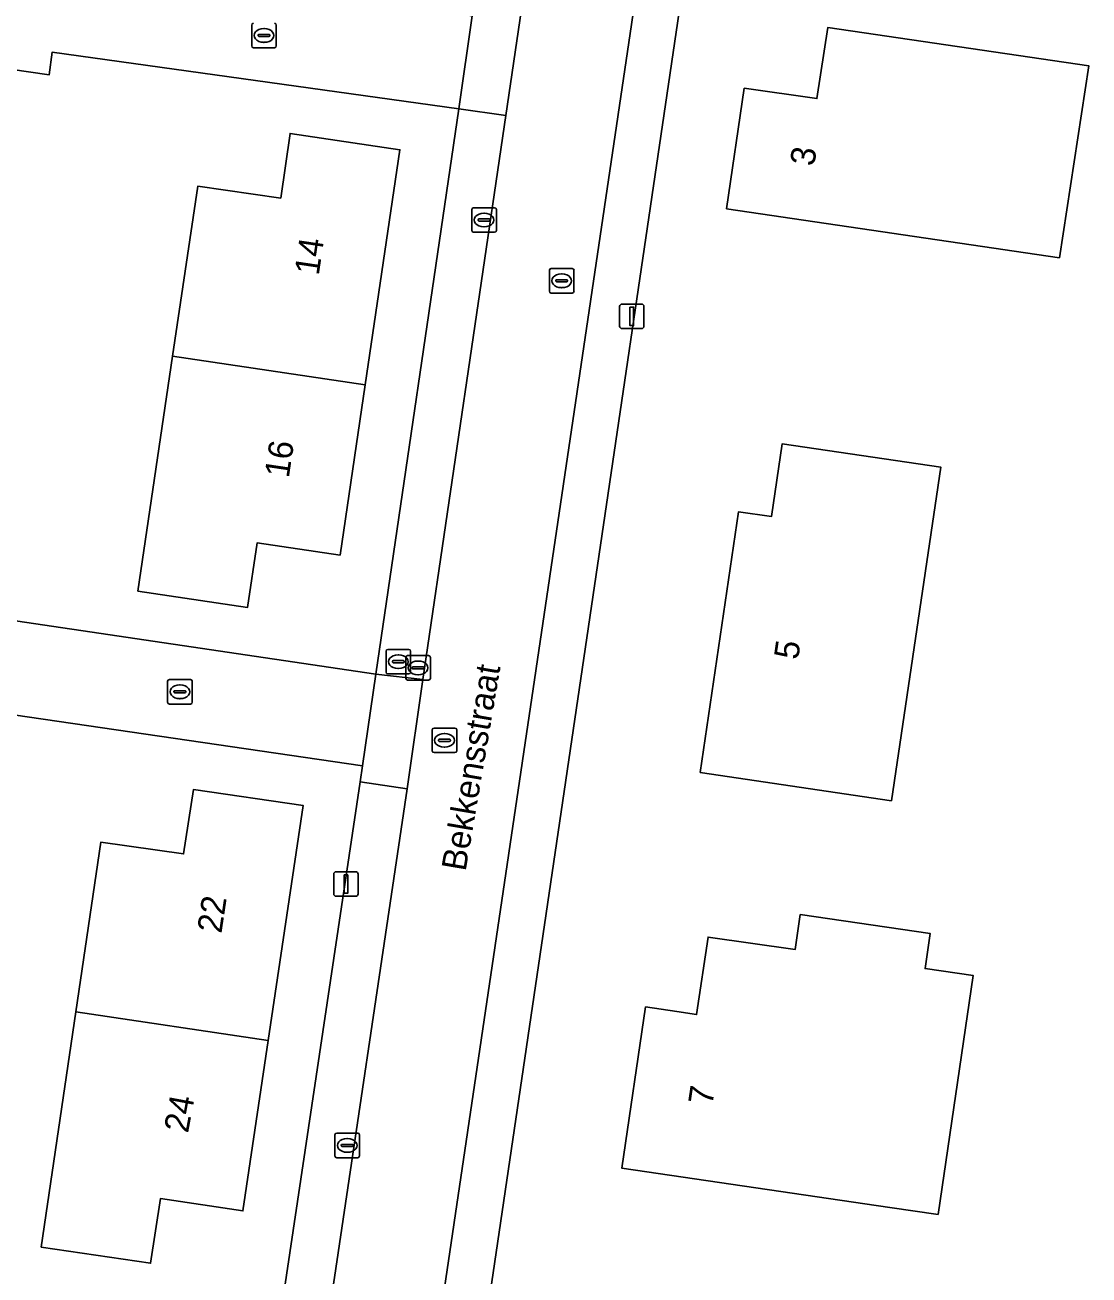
# Model space of a CAD drawing. Extents: x 164148 to 165261, y 382513 to 383432.
# Drawn here: x 164534 to 164577.3, y 383084.8 to 383135.7 of the extents above; entities that cross this region are included whole.
import ezdxf

# ---------------------------------------------------------------- set-up
doc = ezdxf.new("R2010")
doc.units = 0
for name, color, linetype in [('IMGEO_Brandkraan', 7, 'Continuous'), ('IMGEO_Erf', 7, 'Continuous'), ('IMGEO_Kolk', 7, 'Continuous'), ('IMGEO_Lichtmast', 7, 'Continuous'), ('IMGEO_Openbare_ruimte_label', 7, 'Continuous'), ('IMGEO_Pand', 7, 'Continuous'), ('IMGEO_Pand_nummerreeks', 7, 'Continuous'), ('IMGEO_Parkeervlak_open', 7, 'Continuous'), ('IMGEO_Rijbaan_lokaal_open', 7, 'Continuous'), ('IMGEO_Rioolput', 7, 'Continuous'), ('IMGEO_Voetpad_gesloten', 7, 'Continuous'), ('IMGEO_Voetpad_open', 7, 'Continuous')]:
    doc.layers.add(name, color=color, linetype=linetype)

msp = doc.modelspace()

# ---------------------------------------------------------------- linework, layer by layer
at = {"layer": 'IMGEO_Brandkraan'}
for p, q in [((164548.716, 383109.375), (164548.716, 383110.227)), ((164548.791, 383110.301), (164549.643, 383110.301)), ((164549.204, 383110.081), (164549.229, 383110.081)), ((164549.717, 383110.227), (164549.717, 383109.375)), ((164548.975, 383109.795), (164548.975, 383109.807)), ((164549.413, 383109.758), (164549.015, 383109.758)), ((164549.018, 383109.844), (164549.416, 383109.844)), ((164549.227, 383109.521), (164549.202, 383109.521)), ((164549.459, 383109.807), (164549.459, 383109.795)), ((164549.643, 383109.301), (164548.791, 383109.301))]:
    msp.add_line(p, q, dxfattribs=at)
for points in [[(164548.716, 383109.375), (164548.716, 383110.227)], [(164548.791, 383110.301), (164549.643, 383110.301)], [(164549.717, 383110.227), (164549.717, 383109.375)], [(164549.643, 383109.301), (164548.791, 383109.301)]]:
    msp.add_lwpolyline(points, dxfattribs=at)
for centre, radius, start, end in [((164548.793, 383110.225), 0.0765, 91.552, 178.448), ((164548.793, 383110.225), 0.0765, 91.552, 178.448), ((164549.641, 383110.225), 0.0765, 1.552, 88.448), ((164549.641, 383110.225), 0.0765, 1.552, 88.448), ((164548.793, 383109.377), 0.0765, 181.552, 268.448), ((164548.793, 383109.377), 0.0765, 181.552, 268.448), ((164549.015, 383109.804), 0.0403, 85.8775, 175.7526), ((164549.012, 383109.794), 0.0366, 178.938, 274.7102), ((164549.416, 383109.801), 0.043, 264.8664, 352.4533), ((164549.42, 383109.806), 0.0386, 1.7309, 96.639), ((164549.641, 383109.377), 0.0765, 271.552, 358.448), ((164549.641, 383109.377), 0.0765, 271.552, 358.448)]:
    msp.add_arc(centre, radius, start, end, dxfattribs=at)
for centre, major_axis, ratio, start_param, end_param in [((164549.203, 383109.801), (-0.387, 0.002), 0.722429, 4.712389, 7.853982), ((164549.228, 383109.801), (-0.39, 0.002), 0.717154, 1.570796, 4.712389)]:
    msp.add_ellipse(centre, major_axis=major_axis, ratio=ratio, start_param=start_param, end_param=end_param, dxfattribs=at)
at = {"layer": 'IMGEO_Erf'}
for points in [[(164565.964, 383171.957), (164565.828, 383171.331), (164551.479, 383074.055)], [(164543.77, 383078.815), (164527.251, 383081.278), (164527.096, 383080.294), (164518.396, 383081.622), (164519.234, 383087.238), (164527.964, 383085.921), (164527.82, 383085.027), (164544.333, 383082.591), (164544.353, 383082.732), (164547.655, 383104.909), (164547.751, 383105.555), (164531.213, 383107.98), (164531.036, 383107.046), (164522.384, 383108.335), (164523.232, 383113.969), (164531.91, 383112.69), (164531.787, 383111.738), (164548.298, 383109.287), (164551.681, 383132.307), (164535.127, 383134.626), (164535.003, 383133.703), (164526.293, 383134.964), (164527.137, 383140.654)]]:
    msp.add_lwpolyline(points, dxfattribs=at)
for points in [[(164576.136, 383126.247), (164562.579, 383128.243), (164563.303, 383133.153), (164566.262, 383132.73), (164566.698, 383135.619), (164577.338, 383134.061)], [(164540.026, 383122.235), (164541.048, 383129.163), (164544.431, 383128.68), (164544.806, 383131.308), (164549.279, 383130.643), (164547.866, 383121.077), (164546.841, 383114.14), (164543.471, 383114.64), (164543.08, 383112.008), (164538.615, 383112.678)], [(164569.297, 383104.138), (164561.506, 383105.29), (164563.068, 383115.906), (164564.412, 383115.718), (164564.844, 383118.666), (164571.299, 383117.721)], [(164536.085, 383095.54), (164537.103, 383102.451), (164540.471, 383101.97), (164540.877, 383104.598), (164545.334, 383103.946), (164543.918, 383094.38), (164542.889, 383087.434), (164539.529, 383087.938), (164539.13, 383085.305), (164534.674, 383085.96)], [(164570.872, 383098.729), (164570.665, 383097.304), (164572.624, 383097.019), (164571.195, 383087.29), (164569.23, 383087.578), (164558.312, 383089.18), (164559.282, 383095.74), (164560.554, 383095.551), (164561.359, 383095.431), (164561.828, 383098.589), (164565.371, 383098.074), (164565.578, 383099.499)]]:
    msp.add_lwpolyline(points, close=True, dxfattribs=at)
at = {"layer": 'IMGEO_Kolk'}
for p, q in [((164543.246, 383134.874), (164543.246, 383135.726)), ((164543.548, 383135.343), (164543.946, 383135.343)), ((164543.734, 383135.58), (164543.759, 383135.58)), ((164544.247, 383135.726), (164544.247, 383134.874)), ((164543.505, 383135.294), (164543.505, 383135.306)), ((164543.943, 383135.257), (164543.545, 383135.257)), ((164543.757, 383135.02), (164543.732, 383135.02)), ((164543.989, 383135.306), (164543.989, 383135.294)), ((164544.173, 383134.8), (164543.321, 383134.8)), ((164552.206, 383127.36), (164552.206, 383128.212)), ((164552.281, 383128.286), (164553.133, 383128.286)), ((164553.207, 383128.212), (164553.207, 383127.36)), ((164552.465, 383127.78), (164552.465, 383127.792)), ((164552.903, 383127.743), (164552.505, 383127.743)), ((164552.508, 383127.829), (164552.906, 383127.829)), ((164552.694, 383128.066), (164552.719, 383128.066)), ((164552.949, 383127.792), (164552.949, 383127.78)), ((164553.133, 383127.286), (164552.281, 383127.286)), ((164552.717, 383127.506), (164552.692, 383127.506)), ((164549.519, 383109.12), (164549.519, 383109.972)), ((164549.594, 383110.046), (164550.446, 383110.046)), ((164550.52, 383109.972), (164550.52, 383109.12)), ((164549.778, 383109.54), (164549.778, 383109.552)), ((164550.216, 383109.503), (164549.818, 383109.503)), ((164549.821, 383109.589), (164550.219, 383109.589)), ((164550.007, 383109.826), (164550.032, 383109.826)), ((164550.262, 383109.552), (164550.262, 383109.54)), ((164539.822, 383108.148), (164539.822, 383109)), ((164539.897, 383109.074), (164540.749, 383109.074)), ((164540.823, 383109), (164540.823, 383108.148)), ((164550.446, 383109.046), (164549.594, 383109.046)), ((164550.03, 383109.266), (164550.005, 383109.266)), ((164540.081, 383108.568), (164540.081, 383108.58)), ((164540.519, 383108.531), (164540.121, 383108.531)), ((164540.124, 383108.617), (164540.522, 383108.617)), ((164540.31, 383108.854), (164540.335, 383108.854)), ((164540.565, 383108.58), (164540.565, 383108.568)), ((164540.749, 383108.074), (164539.897, 383108.074)), ((164540.333, 383108.294), (164540.308, 383108.294)), ((164546.709, 383090.603), (164547.561, 383090.603)), ((164546.634, 383089.677), (164546.634, 383090.529)), ((164546.893, 383090.097), (164546.893, 383090.109)), ((164547.331, 383090.06), (164546.933, 383090.06)), ((164546.936, 383090.146), (164547.334, 383090.146)), ((164547.122, 383090.383), (164547.147, 383090.383)), ((164547.377, 383090.109), (164547.377, 383090.097)), ((164547.635, 383090.529), (164547.635, 383089.677)), ((164547.561, 383089.603), (164546.709, 383089.603)), ((164547.145, 383089.823), (164547.12, 383089.823))]:
    msp.add_line(p, q, dxfattribs=at)
for points in [[(164543.246, 383134.874), (164543.246, 383135.726)], [(164544.247, 383135.726), (164544.247, 383134.874)], [(164544.173, 383134.8), (164543.321, 383134.8)], [(164552.206, 383127.36), (164552.206, 383128.212)], [(164552.281, 383128.286), (164553.133, 383128.286)], [(164553.207, 383128.212), (164553.207, 383127.36)], [(164553.133, 383127.286), (164552.281, 383127.286)], [(164549.519, 383109.12), (164549.519, 383109.972)], [(164549.594, 383110.046), (164550.446, 383110.046)], [(164550.52, 383109.972), (164550.52, 383109.12)], [(164539.822, 383108.148), (164539.822, 383109)], [(164539.897, 383109.074), (164540.749, 383109.074)], [(164540.823, 383109), (164540.823, 383108.148)], [(164550.446, 383109.046), (164549.594, 383109.046)], [(164540.749, 383108.074), (164539.897, 383108.074)], [(164546.709, 383090.603), (164547.561, 383090.603)], [(164546.634, 383089.677), (164546.634, 383090.529)], [(164547.635, 383090.529), (164547.635, 383089.677)], [(164547.561, 383089.603), (164546.709, 383089.603)]]:
    msp.add_lwpolyline(points, dxfattribs=at)
for centre, radius, start, end in [((164543.323, 383135.724), 0.0765, 91.552, 178.448), ((164543.323, 383135.724), 0.0765, 91.552, 178.448), ((164543.545, 383135.303), 0.0403, 85.8775, 175.7526), ((164543.95, 383135.305), 0.0386, 1.7309, 96.639), ((164544.171, 383135.724), 0.0765, 1.552, 88.448), ((164544.171, 383135.724), 0.0765, 1.552, 88.448), ((164543.323, 383134.876), 0.0765, 181.552, 268.448), ((164543.323, 383134.876), 0.0765, 181.552, 268.448), ((164543.542, 383135.293), 0.0366, 178.938, 274.7102), ((164543.946, 383135.3), 0.043, 264.8664, 352.4533), ((164544.171, 383134.876), 0.0765, 271.552, 358.448), ((164544.171, 383134.876), 0.0765, 271.552, 358.448), ((164552.283, 383128.21), 0.0765, 91.552, 178.448), ((164552.283, 383128.21), 0.0765, 91.552, 178.448), ((164553.131, 383128.21), 0.0765, 1.552, 88.448), ((164553.131, 383128.21), 0.0765, 1.552, 88.448), ((164552.505, 383127.789), 0.0403, 85.8775, 175.7526), ((164552.502, 383127.779), 0.0366, 178.938, 274.7102), ((164552.906, 383127.786), 0.043, 264.8664, 352.4533), ((164552.91, 383127.791), 0.0386, 1.7309, 96.639), ((164552.283, 383127.362), 0.0765, 181.552, 268.448), ((164552.283, 383127.362), 0.0765, 181.552, 268.448), ((164553.131, 383127.362), 0.0765, 271.552, 358.448), ((164553.131, 383127.362), 0.0765, 271.552, 358.448), ((164549.596, 383109.97), 0.0765, 91.552, 178.448), ((164549.596, 383109.97), 0.0765, 91.552, 178.448), ((164550.444, 383109.97), 0.0765, 1.552, 88.448), ((164550.444, 383109.97), 0.0765, 1.552, 88.448), ((164549.818, 383109.549), 0.0403, 85.8775, 175.7526), ((164549.815, 383109.539), 0.0366, 178.938, 274.7102), ((164550.219, 383109.546), 0.043, 264.8664, 352.4533), ((164550.223, 383109.551), 0.0386, 1.7309, 96.639), ((164539.899, 383108.998), 0.0765, 91.552, 178.448), ((164539.899, 383108.998), 0.0765, 91.552, 178.448), ((164540.747, 383108.998), 0.0765, 1.552, 88.448), ((164540.747, 383108.998), 0.0765, 1.552, 88.448), ((164549.596, 383109.122), 0.0765, 181.552, 268.448), ((164549.596, 383109.122), 0.0765, 181.552, 268.448), ((164550.444, 383109.122), 0.0765, 271.552, 358.448), ((164550.444, 383109.122), 0.0765, 271.552, 358.448), ((164540.121, 383108.577), 0.0403, 85.8775, 175.7526), ((164540.118, 383108.567), 0.0366, 178.938, 274.7102), ((164540.522, 383108.574), 0.043, 264.8664, 352.4533), ((164540.526, 383108.579), 0.0386, 1.7309, 96.639), ((164539.899, 383108.15), 0.0765, 181.552, 268.448), ((164539.899, 383108.15), 0.0765, 181.552, 268.448), ((164540.747, 383108.15), 0.0765, 271.552, 358.448), ((164540.747, 383108.15), 0.0765, 271.552, 358.448), ((164546.711, 383090.527), 0.0765, 91.552, 178.448), ((164546.711, 383090.527), 0.0765, 91.552, 178.448), ((164547.559, 383090.527), 0.0765, 1.552, 88.448), ((164547.559, 383090.527), 0.0765, 1.552, 88.448), ((164546.933, 383090.106), 0.0403, 85.8775, 175.7526), ((164546.93, 383090.096), 0.0366, 178.938, 274.7102), ((164547.334, 383090.103), 0.043, 264.8664, 352.4533), ((164547.338, 383090.108), 0.0386, 1.7309, 96.639), ((164546.711, 383089.679), 0.0765, 181.552, 268.448), ((164546.711, 383089.679), 0.0765, 181.552, 268.448), ((164547.559, 383089.679), 0.0765, 271.552, 358.448), ((164547.559, 383089.679), 0.0765, 271.552, 358.448)]:
    msp.add_arc(centre, radius, start, end, dxfattribs=at)
for centre, major_axis, ratio, start_param, end_param in [((164543.733, 383135.3), (-0.387, 0.002), 0.722429, 4.712389, 7.853982), ((164543.758, 383135.3), (-0.39, 0.002), 0.717154, 1.570796, 4.712389), ((164552.693, 383127.786), (-0.387, 0.002), 0.722429, 4.712389, 7.853982), ((164552.718, 383127.786), (-0.39, 0.002), 0.717154, 1.570796, 4.712389), ((164550.006, 383109.546), (-0.387, 0.002), 0.722429, 4.712389, 7.853982), ((164550.031, 383109.546), (-0.39, 0.002), 0.717154, 1.570796, 4.712389), ((164540.309, 383108.574), (-0.387, 0.002), 0.722429, 4.712389, 7.853982), ((164540.334, 383108.574), (-0.39, 0.002), 0.717154, 1.570796, 4.712389), ((164547.121, 383090.103), (-0.387, 0.002), 0.722429, 4.712389, 7.853982), ((164547.146, 383090.103), (-0.39, 0.002), 0.717154, 1.570796, 4.712389)]:
    msp.add_ellipse(centre, major_axis=major_axis, ratio=ratio, start_param=start_param, end_param=end_param, dxfattribs=at)
at = {"layer": 'IMGEO_Lichtmast'}
for p, q in [((164558.227, 383123.464), (164558.227, 383124.264)), ((164558.227, 383124.264), (164558.227, 383123.464)), ((164558.327, 383124.364), (164559.117, 383124.364)), ((164559.117, 383124.364), (164558.327, 383124.364)), ((164559.217, 383124.264), (164559.217, 383123.464)), ((164559.217, 383123.464), (164559.217, 383124.264)), ((164559.117, 383123.364), (164558.327, 383123.364)), ((164558.327, 383123.364), (164559.117, 383123.364)), ((164546.687, 383101.245), (164547.477, 383101.245)), ((164547.477, 383101.245), (164546.687, 383101.245)), ((164546.587, 383100.345), (164546.587, 383101.145)), ((164546.587, 383101.145), (164546.587, 383100.345)), ((164547.577, 383101.145), (164547.577, 383100.345)), ((164547.577, 383100.345), (164547.577, 383101.145)), ((164547.477, 383100.245), (164546.687, 383100.245)), ((164546.687, 383100.245), (164547.477, 383100.245))]:
    msp.add_line(p, q, dxfattribs=at)
for points in [[(164558.647, 383124.239), (164558.797, 383124.239), (164558.797, 383123.489), (164558.647, 383123.489), (164558.647, 383124.239)], [(164547.007, 383101.12), (164547.157, 383101.12), (164547.157, 383100.37), (164547.007, 383100.37), (164547.007, 383101.12)]]:
    msp.add_lwpolyline(points, dxfattribs=at)
for centre, start, end in [((164558.327, 383124.264), 90, 180), ((164558.327, 383124.264), 90, 180), ((164559.117, 383124.264), 0, 90), ((164559.117, 383124.264), 360, 90), ((164558.327, 383123.464), 180, 270), ((164558.327, 383123.464), 180, 270), ((164559.117, 383123.464), 270, 0), ((164559.117, 383123.464), 270, 0), ((164546.687, 383101.145), 90, 180), ((164546.687, 383101.145), 90, 180), ((164547.477, 383101.145), 0, 90), ((164547.477, 383101.145), 360, 90), ((164546.687, 383100.345), 180, 270), ((164546.687, 383100.345), 180, 270), ((164547.477, 383100.345), 270, 0), ((164547.477, 383100.345), 270, 0)]:
    msp.add_arc(centre, 0.1, start, end, dxfattribs=at)
at = {"layer": 'IMGEO_Pand'}
for points in [[(164576.136, 383126.247), (164577.338, 383134.061), (164566.698, 383135.619), (164566.262, 383132.73), (164563.303, 383133.153), (164562.579, 383128.243)], [(164547.866, 383121.077), (164549.279, 383130.643), (164544.806, 383131.308), (164544.431, 383128.68), (164541.048, 383129.163), (164540.026, 383122.235)], [(164547.866, 383121.077), (164540.026, 383122.235), (164538.615, 383112.678), (164543.08, 383112.008), (164543.471, 383114.64), (164546.841, 383114.14)], [(164569.297, 383104.138), (164571.299, 383117.721), (164564.844, 383118.666), (164564.412, 383115.718), (164563.068, 383115.906), (164561.506, 383105.29)], [(164536.085, 383095.54), (164543.918, 383094.38), (164545.334, 383103.946), (164540.877, 383104.598), (164540.471, 383101.97), (164537.103, 383102.451)], [(164565.371, 383098.074), (164561.828, 383098.589), (164561.359, 383095.431), (164560.554, 383095.551), (164559.282, 383095.74), (164558.312, 383089.18), (164569.23, 383087.578), (164571.195, 383087.29), (164572.624, 383097.019), (164570.665, 383097.304), (164570.872, 383098.729), (164565.578, 383099.499)], [(164536.085, 383095.54), (164534.674, 383085.96), (164539.13, 383085.305), (164539.529, 383087.938), (164542.889, 383087.434), (164543.918, 383094.38)]]:
    msp.add_lwpolyline(points, close=True, dxfattribs=at)
at = {"layer": 'IMGEO_Parkeervlak_open'}
for points in [[(164551.681, 383132.307), (164548.298, 383109.287), (164550.215, 383109.069), (164553.599, 383132.047)], [(164549.572, 383104.624), (164547.655, 383104.909), (164544.353, 383082.732), (164546.273, 383082.437)]]:
    msp.add_lwpolyline(points, close=True, dxfattribs=at)
at = {"layer": 'IMGEO_Rijbaan_lokaal_open'}
msp.add_lwpolyline([(164549.539, 383073.752), (164564, 383171.523), (164559.577, 383172.163), (164558.194, 383163.135), (164557.556, 383158.76), (164554.236, 383136.372), (164553.599, 383132.047), (164550.215, 383109.069), (164549.572, 383104.624), (164546.273, 383082.437), (164545.694, 383078.509), (164544.478, 383070.86)], dxfattribs=at)
for points in [[(164551.681, 383132.307), (164552.227, 383136.096), (164535.688, 383138.427), (164535.828, 383139.363), (164527.137, 383140.654), (164526.293, 383134.964), (164535.003, 383133.703), (164535.127, 383134.626)], [(164548.298, 383109.287), (164531.787, 383111.738), (164531.91, 383112.69), (164523.232, 383113.969), (164522.384, 383108.335), (164531.036, 383107.046), (164531.213, 383107.98), (164547.751, 383105.555)]]:
    msp.add_lwpolyline(points, close=True, dxfattribs=at)
at = {"layer": 'IMGEO_Rioolput'}
for p, q in [((164555.367, 383124.884), (164555.367, 383125.736)), ((164555.442, 383125.81), (164556.294, 383125.81)), ((164556.368, 383125.736), (164556.368, 383124.884)), ((164555.626, 383125.304), (164555.626, 383125.316)), ((164556.064, 383125.267), (164555.666, 383125.267)), ((164555.669, 383125.353), (164556.067, 383125.353)), ((164555.855, 383125.59), (164555.88, 383125.59)), ((164556.11, 383125.316), (164556.11, 383125.304)), ((164556.294, 383124.81), (164555.442, 383124.81)), ((164555.878, 383125.03), (164555.853, 383125.03)), ((164550.594, 383106.171), (164550.594, 383107.023)), ((164550.669, 383107.097), (164551.521, 383107.097)), ((164551.082, 383106.877), (164551.107, 383106.877)), ((164551.595, 383107.023), (164551.595, 383106.171)), ((164550.853, 383106.591), (164550.853, 383106.603)), ((164551.291, 383106.554), (164550.893, 383106.554)), ((164550.896, 383106.64), (164551.294, 383106.64)), ((164551.105, 383106.317), (164551.08, 383106.317)), ((164551.337, 383106.603), (164551.337, 383106.591)), ((164551.521, 383106.097), (164550.669, 383106.097))]:
    msp.add_line(p, q, dxfattribs=at)
for points in [[(164555.367, 383124.884), (164555.367, 383125.736)], [(164555.442, 383125.81), (164556.294, 383125.81)], [(164556.368, 383125.736), (164556.368, 383124.884)], [(164556.294, 383124.81), (164555.442, 383124.81)], [(164550.594, 383106.171), (164550.594, 383107.023)], [(164550.669, 383107.097), (164551.521, 383107.097)], [(164551.595, 383107.023), (164551.595, 383106.171)], [(164551.521, 383106.097), (164550.669, 383106.097)]]:
    msp.add_lwpolyline(points, dxfattribs=at)
for centre, radius, start, end in [((164555.444, 383125.734), 0.0765, 91.552, 178.448), ((164555.444, 383125.734), 0.0765, 91.552, 178.448), ((164556.292, 383125.734), 0.0765, 1.552, 88.448), ((164556.292, 383125.734), 0.0765, 1.552, 88.448), ((164555.666, 383125.313), 0.0403, 85.8775, 175.7526), ((164555.663, 383125.303), 0.0366, 178.938, 274.7102), ((164556.067, 383125.31), 0.043, 264.8664, 352.4533), ((164556.071, 383125.315), 0.0386, 1.7309, 96.639), ((164555.444, 383124.886), 0.0765, 181.552, 268.448), ((164555.444, 383124.886), 0.0765, 181.552, 268.448), ((164556.292, 383124.886), 0.0765, 271.552, 358.448), ((164556.292, 383124.886), 0.0765, 271.552, 358.448), ((164550.671, 383107.021), 0.0765, 91.552, 178.448), ((164550.671, 383107.021), 0.0765, 91.552, 178.448), ((164551.519, 383107.021), 0.0765, 1.552, 88.448), ((164551.519, 383107.021), 0.0765, 1.552, 88.448), ((164550.893, 383106.6), 0.0403, 85.8775, 175.7526), ((164550.89, 383106.59), 0.0366, 178.938, 274.7102), ((164551.294, 383106.597), 0.043, 264.8664, 352.4533), ((164551.298, 383106.602), 0.0386, 1.7309, 96.639), ((164550.671, 383106.173), 0.0765, 181.552, 268.448), ((164550.671, 383106.173), 0.0765, 181.552, 268.448), ((164551.519, 383106.173), 0.0765, 271.552, 358.448), ((164551.519, 383106.173), 0.0765, 271.552, 358.448)]:
    msp.add_arc(centre, radius, start, end, dxfattribs=at)
for centre, major_axis, ratio, start_param, end_param in [((164555.854, 383125.31), (-0.387, 0.002), 0.722429, 4.712389, 7.853982), ((164555.879, 383125.31), (-0.39, 0.002), 0.717154, 1.570796, 4.712389), ((164551.081, 383106.597), (-0.387, 0.002), 0.722429, 4.712389, 7.853982), ((164551.106, 383106.597), (-0.39, 0.002), 0.717154, 1.570796, 4.712389)]:
    msp.add_ellipse(centre, major_axis=major_axis, ratio=ratio, start_param=start_param, end_param=end_param, dxfattribs=at)
at = {"layer": 'IMGEO_Voetpad_gesloten'}
msp.add_lwpolyline([(164551.479, 383074.055), (164565.828, 383171.331), (164564.021, 383171.63), (164564, 383171.523), (164549.539, 383073.752)], dxfattribs=at)
at = {"layer": 'IMGEO_Voetpad_open'}
for points in [[(164554.236, 383136.372), (164552.31, 383136.657), (164552.227, 383136.096), (164551.681, 383132.307), (164553.599, 383132.047)], [(164550.215, 383109.069), (164548.298, 383109.287), (164547.751, 383105.555), (164547.655, 383104.909), (164549.572, 383104.624)]]:
    msp.add_lwpolyline(points, close=True, dxfattribs=at)

# ---------------------------------------------------------------- texts
at = {"layer": 'IMGEO_Openbare_ruimte_label'}
msp.add_text('Bekkensstraat', height=1, rotation=80.3305, dxfattribs=at).set_placement((164551.953, 383101.235))
at = {"layer": 'IMGEO_Pand_nummerreeks'}
for s, rotation, p in [('3', 81.6192, (164566.146, 383129.951)), ('14', 81.5969, (164545.973, 383125.504)), ('16', 81.5969, (164544.754, 383117.253)), ('5', 81.628, (164565.492, 383109.852)), ('22', 81.5747, (164542.012, 383098.711)), ('24', 79.504, (164540.65, 383090.577)), ('7', 81.5901, (164562.002, 383091.712))]:
    msp.add_text(s, height=1, rotation=rotation, dxfattribs=at).set_placement(p)

doc.saveas('drawing.dxf')
